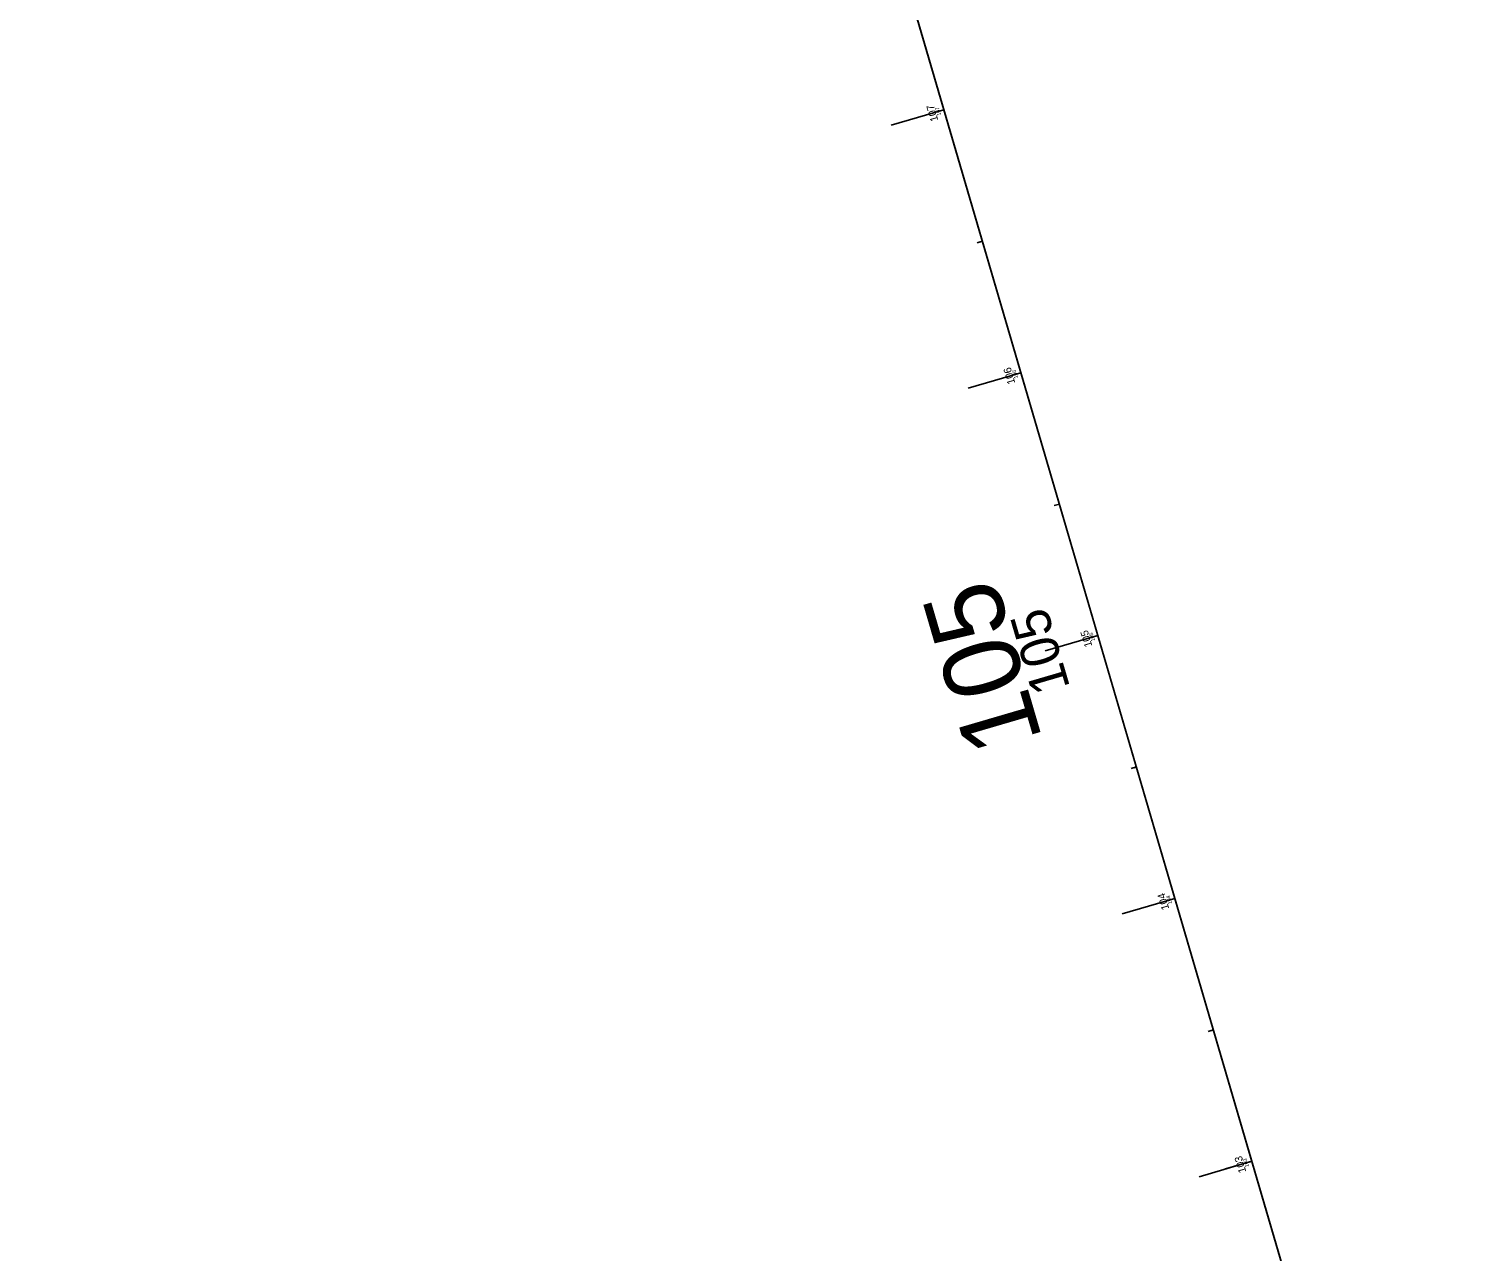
# Model space of a CAD drawing. Extents: x 1794716 to 1797874, y 325521 to 329174.
# Drawn here: x 1796270 to 1796801, y 325968 to 326414 of the extents above; entities that cross this region are included whole.
import ezdxf

# ---------------------------------------------------------------- set-up
doc = ezdxf.new("R2010")
doc.units = 0
for name, color, linetype in [('GE_P_CL_10', 7, 'Continuous'), ('GE_P_CL_100', 7, 'Continuous'), ('GE_P_CL_20', 7, 'Continuous'), ('GE_P_CL_200', 7, 'Continuous'), ('RW_X_CL_20', 7, 'Continuous')]:
    doc.layers.add(name, color=color, linetype=linetype)

msp = doc.modelspace()

# ---------------------------------------------------------------- linework, layer by layer
at = {"layer": 'GE_P_CL_10'}
for p, q in [((1796800.73, 325712.87), (1796269.93, 327524.51)), ((1796603.91, 326384.63), (1796602.95, 326384.35)), ((1796617.97, 326336.65), (1796617.01, 326336.37)), ((1796632.03, 326288.66), (1796631.07, 326288.38)), ((1796646.08, 326240.68), (1796645.13, 326240.4)), ((1796660.14, 326192.7), (1796659.18, 326192.42)), ((1796674.2, 326144.72), (1796673.24, 326144.43)), ((1796688.26, 326096.73), (1796687.3, 326096.45)), ((1796702.32, 326048.75), (1796701.36, 326048.47)), ((1796716.38, 326000.77), (1796715.42, 326000.49))]:
    msp.add_line(p, q, dxfattribs=at)
at = {"layer": 'GE_P_CL_100'}
for p, q in [((1796800.73, 325712.87), (1796269.93, 327524.51)), ((1796603.91, 326384.63), (1796594.31, 326381.82)), ((1796632.03, 326288.66), (1796622.43, 326285.85)), ((1796660.14, 326192.7), (1796650.55, 326189.89)), ((1796688.26, 326096.73), (1796678.66, 326093.92)), ((1796716.38, 326000.77), (1796706.78, 325997.96))]:
    msp.add_line(p, q, dxfattribs=at)
at = {"layer": 'GE_P_CL_20'}
for p, q in [((1796800.73, 325712.87), (1796269.93, 327524.51)), ((1796603.91, 326384.63), (1796601.99, 326384.07)), ((1796617.97, 326336.65), (1796616.05, 326336.08)), ((1796632.03, 326288.66), (1796630.11, 326288.1)), ((1796646.08, 326240.68), (1796644.17, 326240.12)), ((1796660.14, 326192.7), (1796658.22, 326192.14)), ((1796674.2, 326144.72), (1796672.28, 326144.15)), ((1796688.26, 326096.73), (1796686.34, 326096.17)), ((1796702.32, 326048.75), (1796700.4, 326048.19)), ((1796716.38, 326000.77), (1796714.46, 326000.2))]:
    msp.add_line(p, q, dxfattribs=at)
at = {"layer": 'GE_P_CL_200'}
for p, q in [((1796800.73, 325712.87), (1796269.93, 327524.51)), ((1796603.91, 326384.63), (1796584.72, 326379.01)), ((1796632.03, 326288.66), (1796612.83, 326283.04)), ((1796660.14, 326192.7), (1796640.95, 326187.08)), ((1796688.26, 326096.73), (1796669.07, 326091.11)), ((1796716.38, 326000.77), (1796697.19, 325995.14))]:
    msp.add_line(p, q, dxfattribs=at)
at = {"layer": 'RW_X_CL_20'}
msp.add_lwpolyline([(1796800.73, 325712.87), (1796269.93, 327524.51)], dxfattribs=at)

# ---------------------------------------------------------------- texts
at = {"layer": 'GE_P_CL_10'}
for s, p in [('107', (1796602.91, 326382.7)), ('106', (1796631.02, 326286.76)), ('105', (1796659.14, 326190.8)), ('104', (1796687.25, 326094.85)), ('103', (1796715.37, 325998.86))]:
    msp.add_text(s, height=1.4, rotation=106.3303, dxfattribs=at).set_placement(p)
at = {"layer": 'GE_P_CL_100'}
msp.add_text('105', height=14, rotation=106.3303, dxfattribs=at).set_placement((1796650.07, 326173.73))
at = {"layer": 'GE_P_CL_20'}
for s, p in [('107', (1796601.91, 326380.77)), ('106', (1796630.01, 326284.86)), ('105', (1796658.13, 326188.9)), ('104', (1796686.24, 326092.97)), ('103', (1796714.37, 325996.96))]:
    msp.add_text(s, height=2.8, rotation=106.3303, dxfattribs=at).set_placement(p)
at = {"layer": 'GE_P_CL_200'}
msp.add_text('105', height=28, rotation=106.3303, dxfattribs=at).set_placement((1796640, 326154.76))

doc.saveas('drawing.dxf')
